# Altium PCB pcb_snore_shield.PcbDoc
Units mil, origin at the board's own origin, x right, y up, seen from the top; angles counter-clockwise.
Board outline 6000 x 4000 mil, 2 copper layers (Top Layer, Bottom Layer); 51 components, 37 nets, 162 pads, 19 vias.
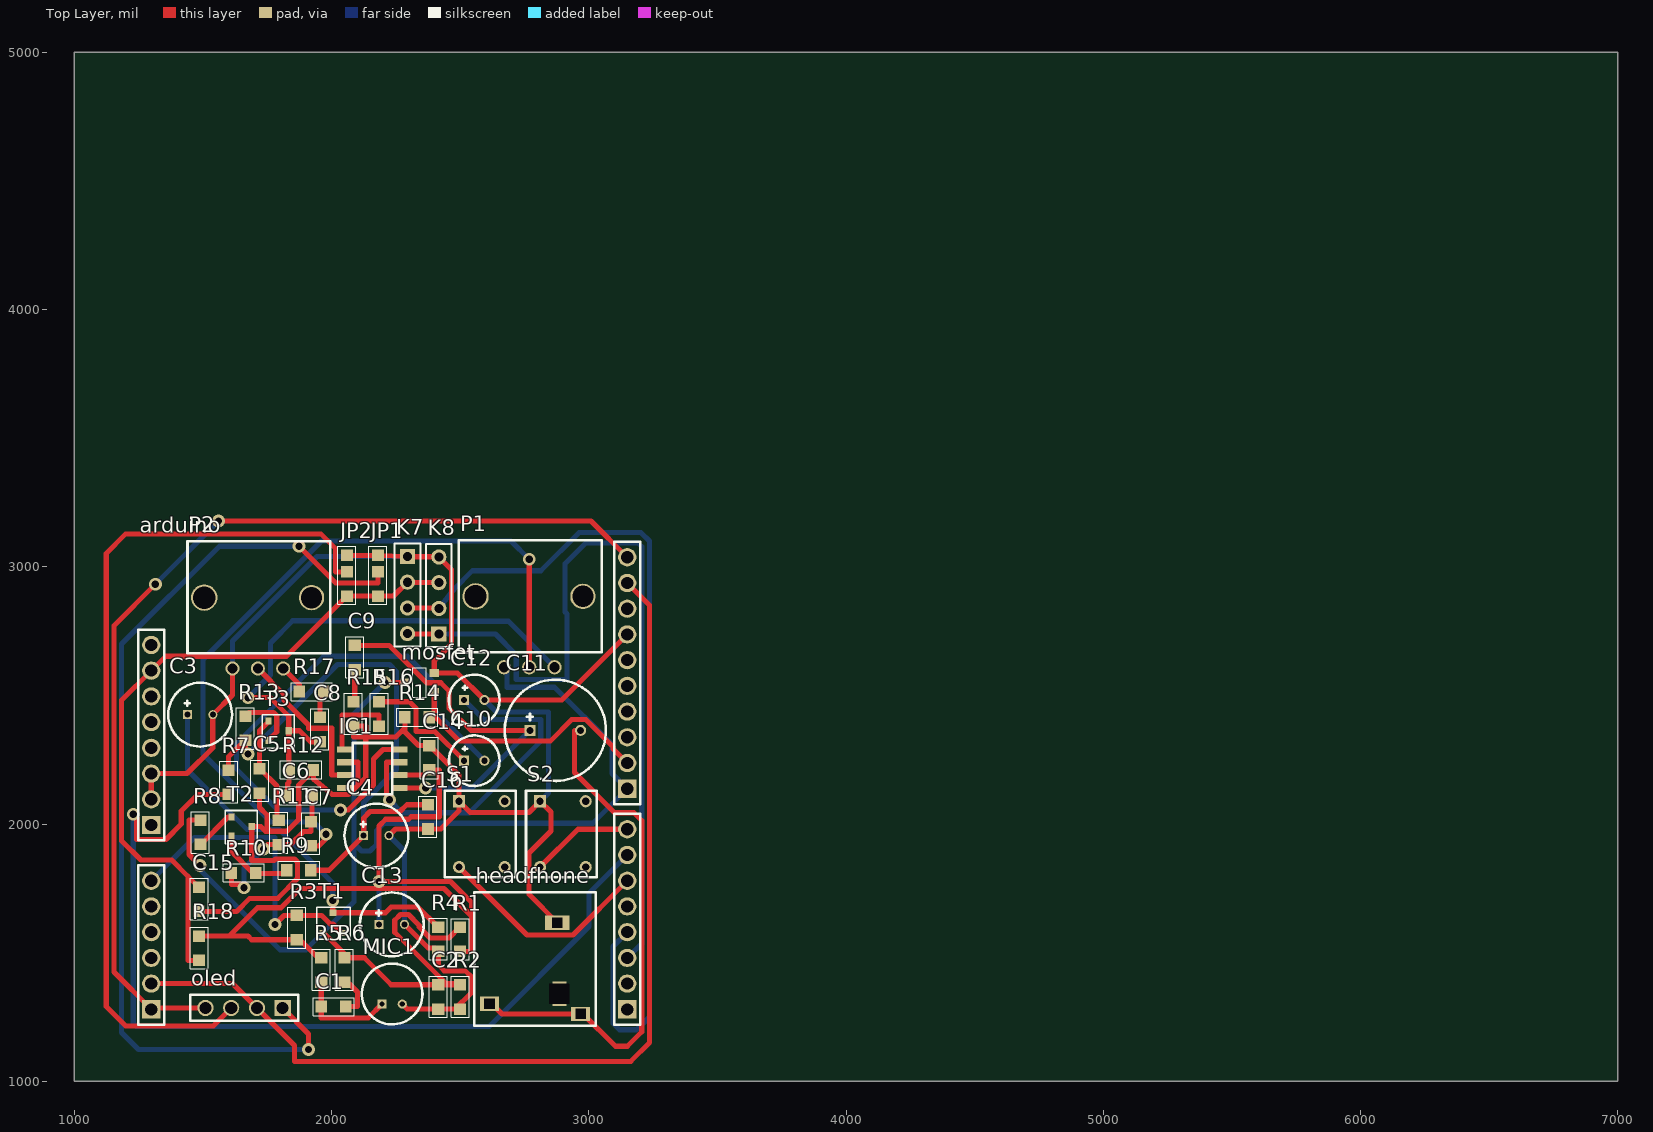
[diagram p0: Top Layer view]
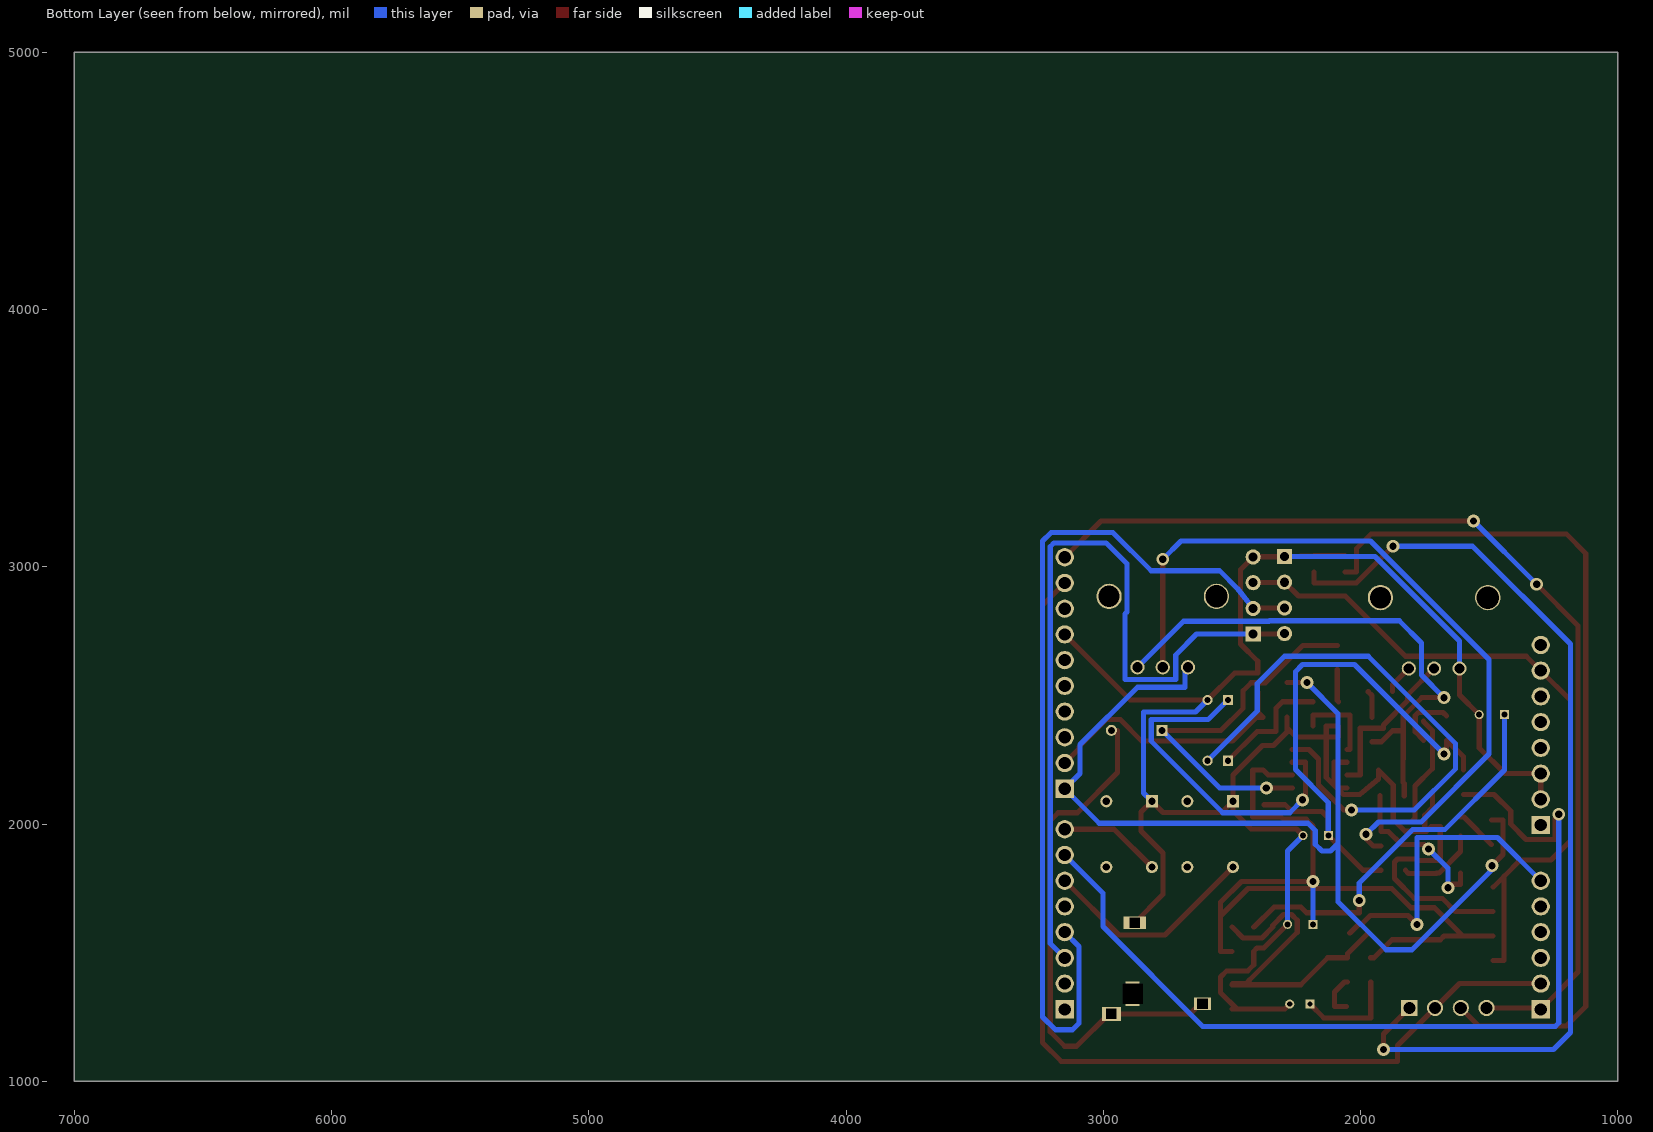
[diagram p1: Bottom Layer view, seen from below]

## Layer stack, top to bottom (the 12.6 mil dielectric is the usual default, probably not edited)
Top Solder: solder mask 0.4, Solder Resist, Dk 3.5
Top Layer: signal copper 1.4
Dielectric 1: dielectric 12.6, FR-4, Dk 4.8
Bottom Layer: signal copper 1.4
Bottom Solder: solder mask 0.4, Solder Resist, Dk 3.5

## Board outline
1000,1000 7000,1000 7000,5000 1000,5000

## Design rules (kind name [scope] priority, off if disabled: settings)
Clearance [All] p1: gap=10 ignorepadtopadclearanceinfootprint=FALSE except(0: Arc-Hole Track-Hole SMDPad-Hole THPad-Hole Via-Hole Fill-Hole Poly-Hole Region-Hole Text-Hole)
PolygonConnect [All] p1: connectstyle=Relief reliefconductorwidth=10 reliefentries=4 polygonreliefangle="90 Angle" airgapwidth=10
RoomDefinition snor_shield_sheet [InComponentClass('snor_shield_sheet')] p1: confinementstyle=ConfineIn formatcopy=TRUE lockcomponents=FALSE outline 7178.7,2815 20768.7,2815 20768.7,5240 7178.7,5240
RoutingVias [All] p1: holewidth=28 width=50 viastyle="Through Hole" minholewidth=28 minwidth=50 maxholewidth=28 maxwidth=50
SolderMaskExpansion [All] p1: expansion=4 istentingtop=FALSE
Width [All] p1: maxlimit=20 minlimit=20 preferedwidth=20
30 further rules are at their usual default settings.

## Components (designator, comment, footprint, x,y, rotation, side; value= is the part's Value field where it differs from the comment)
arduino "arduino r3 shield" arduino 1299.21,1279.53 r0 top
C1 "Capitor" "SMD 0805" 1948.19,1290 r0 top value=1µF
C2 "Capitor" "SMD 0805" 2415,1268.7 r90 top value=100nF
C3 "Cap Pol1" "elektor trans 2" 1440,2425 r0 top value=47µF/16V
C4 "Cap Pol1" "elektor trans 2" 2125,1955 r0 top value=47µF/16V
C5 "Capitor" "SMD 0805" 1720,2108.19 r90 top value=100pF
C6 "Capitor" "SMD 0805" 1818.19,2110 r0 top value=100pF
C7 "Capitor" "SMD 0805" 1920,1903.19 r90 top value=1nF
C8 "Capitor" "SMD 0805" 1955,2308.19 r90 top value=1µF
C9 "Capitor" "SMD 0805" 2090,2588.19 r90 top value=47nF
C10 "Cap Pol1" "elecktor trans 1" 2515.59,2245.98 r0 top value=10µF/16V
C11 "Cap Pol1" "elektor trans 3" 2771.5,2364.09 r0 top value=220µF/16V
C12 "Cap Pol1" "elecktor trans 1" 2515.59,2482.2 r0 top value=10µF/16V
C13 "Cap Pol1" "elektor trans 2" 2185,1610 r0 top value=47µF/16V
C14 "Cap" "SMD 0805" 2380,2316.81 r270 top value=100nF
C15 "Capitor" "SMD 0805" 1485,1648.19 r90 top value=100nF
C16 "Capitor" "SMD 0805" 2375,1968.7 r90 top value=100nF
headfhone "K-JACK-STEREO-3.5MM" adioplug3.5mm 2614.02,1301.1 r0 top
IC1 "LM386M-1/NOPB" LM386M-1/NOPB 2052.4,2290 r0 top
JP1 "Res2" soldeer_jumper 2180,2874.02 r90 top value=0Ohm
JP2 "Res2" soldeer_jumper 2060,2874.02 r90 top value=0Ohm
K7 "Header 4" HDR1X4 2295,3040 r270 top
K8 "Header 4" HDR1X4 2417.17,2738.11 r90 top (schematic designator K6)
MIC1 "Mic2" "Electret Condenser Microphone" 2196.26,1300 r0 top
mosfet "power MOSFET" "power mosfet" 2285,2550 r90 top
oled "1X4 socked" "oled scherm" 1810,1285 r180 top
P1 "Res Adj2" potmeter 2560,2885 r0 top value=100k
P2 "Res Adj2" potmeter 1505,2880 r0 top value=10K
R1 "weerstand" "SMD 0805" 2500,1611.3 r270 top value=27K
R2 "weerstand" "SMD 0805" 2500,1268.7 r90 top value=15K
R3 "weerstand" "SMD 0805" 1865,1656.3 r270 top value=27K
R4 "weerstand" "SMD 0805" 2415,1493.19 r90 top value=1K2
R5 "weerstand" "SMD 0805" 1960,1373.7 r90 top value=10K
R6 "weerstand" "SMD 0805" 2050,1373.7 r90 top value=680Ohm
R7 "weerstand" "SMD 0805" 1600,2103.19 r90 top value=10K
R8 "weerstand" "SMD 0805" 1490,2026.81 r270 top value=10K
R9 "weerstand" "SMD 0805" 1813.7,1820 r0 top value=10K
R10 "weerstand" "SMD 0805" 1598.7,1810 r0 top value=180K
R11 "weerstand" "SMD 0805" 1795,2026.3 r270 top value=180K
R12 "weerstand" "SMD 0805" 1941.3,2210 r180 top value=10K
R13 "weerstand" "SMD 0805" 1665,2431.3 r270 top value=1K
R14 "weerstand" "SMD 0805" 2273.7,2415 r0 top value=100K
R15 "weerstand" "SMD 0805" 2085,2368.7 r90 top value=10Ohm
R16 "weerstand" "SMD 0805" 2185,2368.7 r90 top value=1K
R17 "Res2" "SMD 0805" 1863.19,2515 r0 top value=100K
R18 "weerstand" "SMD 0805" 1485,1458.19 r90 top value=10Ohm
S1 "SW-PB" switch 2495.91,2088.5 r0 top
S2 "SW-PB" switch 2810.87,2088.5 r0 top
T1 "BC847C" "bipolar BjT" 2042.4,1576.26 r180 top
T2 "BC847C" "bipolar BjT" 1611.26,1952.6 r90 top
T3 "BC847C" "bipolar BjT" 1755,2325 r90 top

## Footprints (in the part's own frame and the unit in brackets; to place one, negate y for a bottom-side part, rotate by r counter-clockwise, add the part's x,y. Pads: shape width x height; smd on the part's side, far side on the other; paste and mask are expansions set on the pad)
adioplug3.5mm [mm]
  rect 1.4x2.4 hole 2 square: B(6.9,1)
  rect 1.9x1.4 hole 1 square: R(9,-1)
  rect 2.4x1.4 / inner rect 2.2x1.27 / far side rect 2.2x1.2 hole 1 square: S(6.7,8)
  rect 1.9x1.4 / inner rect 2.54x1.27 / far side rect 1.7x1.2 hole 1 square: T(0,0)
  silkscreen extent -1.5,-2.16 10.5,11
arduino [mm]
  round 1.8 hole 1.2: 3.3V(0,28.36) 5V(0,25.82) 14(0,35.98) A0/PC0(0,12.7) A1/PC1(0,10.16) A2/PC2(0,7.62) A3/PC3(0,5.08) A4/PC4(0,2.54) A4/PC4(47,42.1) A5/PC5(47,44.64) AREF(47,39.56) GND(0,20.74) GND(0,23.28) GND(47,37.02) INT0/PD2(47,5.08) INT1/PD3(47,7.62) IOREF(0,33.44) MISO/PB4(47,31.94) MOSI/PB3(47,29.4) PB1(47,24.32) PD4(47,10.16) PD5(47,12.7) PD6(47,15.24) PD7(47,17.78) RST/PC6(0,30.9) SCK/PB5(47,34.48) SS/PB2(47,26.86) TX/PD1(47,2.54)
  rect 1.8x1.8 hole 1.2: A5/PC5(0,0) PB0(47,21.78) RX/PD0(47,0) VIN(0,18.2)
  silkscreen extent -1.27,-1.52 48.27,46.16
"bipolar BjT" [mm]
  rect 0.7x0.6 smd: 1(1.9,0) 2(0,0) 3(0.95,-2)
  silkscreen extent -0.76,-2.54 2.54,0.63
"elecktor trans 1" [mm]
  rect 1x1 hole 0.6: 1(0,0)
  round 1 hole 0.6: 2(2,0)
  silkscreen extent -1.5,-2.5 3.5,2.5
"Electret Condenser Microphone" [mm]
  rect 0.9x0.9 hole 0.5: 1(0,0)
  round 0.9 hole 0.5: 2(2,0)
  silkscreen extent -2,-2 4,4
"elektor trans 2" [mm]
  rect 0.9x0.9 hole 0.6: 1(0,0)
  round 0.9 hole 0.6: 2(2.5,0)
  silkscreen extent -1.9,-3.15 4.4,3.15
"elektor trans 3" [mm]
  rect 1.1x1.1 hole 0.7: 1(0,0)
  round 1.1 hole 0.7: 2(5,0)
  silkscreen extent -2.5,-5 7.5,5
HDR1X4 [mm] "Connector; Header; 4 Position"
  rect 1.5x1.5 hole 0.9: 1(0,0)
  round 1.5 hole 0.9: 2(2.54,0) 3(5.08,0) 4(7.62,0)
  silkscreen extent -1.27,-1.27 8.89,1.27
LM386M-1/NOPB [mm]
  rect 1.55x0.6 smd: 1(0,0) 2(0,-1.27) 3(0,-2.54) 4(0,-3.81) 5(5.4,-3.81) 6(5.4,-2.54) 7(5.4,-1.27) 8(5.4,0)
  silkscreen extent 0.75,-4.44 4.65,0.64
"oled scherm" [mm]
  rect 1.6x1.6 hole 1.2: 1(0,0)
  round 1.6 hole 1.2: 2(5.08,0) 3(7.62,0) 4(2.54,0)
  silkscreen extent -1.52,-1.29 9.14,1.25
potmeter [mm]
  round 1.4 hole 1: 1(2.8,-7) 2(5.3,-7)
  round 1.4 / inner oval 1.4x0.064 / far side round 1.4 hole 1: 3(7.8,-7)
  round 2.5 / inner oval 2.5x0.064 / far side round 2.5 hole 2.1: 4(10.6,0)
  round 2.6 / inner round 2.5 / far side round 2.5 hole 2.2: 5(0,0)
  silkscreen extent -1.65,-5.5 12.45,5.55
"power mosfet" [mm]
  rect 0.8x0.9 smd: 1(-0.95,-2.9) 2(0.95,-2.9) 3(0,0)
  silkscreen extent -1.45,-2.1 1.45,-0.8
"SMD 0805" [mm]
  rect 1.14x1.2 smd: 1(0.3,0) 2(2.7,0)
  silkscreen extent -0.51,-0.89 3.56,0.89
soldeer_jumper [mm]
  rect 1.14x1.2 smd: 1(0.3,0) 2(2.7,0) 3(4.318,0)
  silkscreen extent -0.51,-0.89 5.21,0.89
switch [mm]
  rect 1.2x1.2 hole 0.71: 1(0,0)
  round 1.2 hole 0.71: 2(0,-6.5) 3(4.5,-6.5) 4(4.5,0)
  silkscreen extent -1.4,-7.49 5.59,1.02

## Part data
C1 C2 C5 C6 C7 C8 C9 C15 C16: "Capacitor"
C3 C4 C13: library part "Cap Pol1_1", "Polarized Capacitor (Radial) 47µF"
C10 C12: "Polarized Capacitor (Radial) 10µF"
C11: library part "Cap Pol1_2", "Polarized Capacitor (Radial) 220µF"
C14: library part Capitor, "Capacitor"
JP1 JP2: library part solderjump, "Resistor"
K7: "Header, 4-Pin,2mm"
K8: "Header, 4-Pin"
MIC1: "Microphone"
P1: "Variable Resistor 10K"
P2: library part "Res Adj2_1", "Variable Resistor"
R1 R2 R3 R4 R5 R6 R7 R8 R9 R10 R11 R12 R13 R14 R15 R16 R18: "Resistor"
R17: library part weerstand, "Resistor"
S1 S2: library part switch, "Switch"
T1 T2 T3: library part BJT, "NPN General Purpose Amplifier"

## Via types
v1: diameter 50, hole 28, Top Layer to Bottom Layer, 19 vias

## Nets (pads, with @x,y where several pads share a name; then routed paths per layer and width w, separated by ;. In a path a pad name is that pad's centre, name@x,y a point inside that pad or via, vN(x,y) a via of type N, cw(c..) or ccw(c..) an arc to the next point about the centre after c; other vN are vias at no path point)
+5V: C13.1 C14.2 IC1.6 R1.2 R3.2 R5.2 R18.2 | length 3176.2
  Top Layer w20: R18.2 1602.14,1564.49 ; R5.2 1947,1480 1877,1550 R3.2 1689.49,1550 1675,1564.49 1602.14,1564.49 ; IC1.6 2358.31,2190 2378.82,2210.51 C14.2 2419,2210.51 2419,2028 2309.53,2028 2299.71,2018.19 2210.89,2018.19 2185,1992.29 v1(2185,1777) 2463,1777 2544,1696 2544,1642 ; R1.2 2544,1505 2544,1642 ; 1602.14,1564.49 1712.14,1674.49 1803.49,1674.49 1878,1749 2437,1749 2544,1642
  Bottom Layer w20: C13.1 v1(2185,1777)
GND: arduino.GND C2.1 C3.2 C4.2 C5.1 C12.2 C13.2 C14.1 C15.1 C16.1 headfhone.S IC1.2 IC1.4 JP1.3 JP2.3 K7.1 K8.4 MIC1.2 mosfet.2 P2.1 R2.1 R4.1 R12.1 R14.1 R15.1 S1.1 S2.1 T2.3 | length 9249.8
  Top Layer w20: arduino.GND@1299.21,2096.06 1299.21,2196.06 1438.62,2196.06 1538.43,2295.87 C3.2 1615.24,2501.81 P2.1 ; C15.1 1631.2,1660 1682.14,1710.94 1790.8,1710.94 1867.95,1788.09 1867.95,1851.91 1856.24,1863.62 1781.97,1863.62 1775.98,1857.63 1690,1857.63 T2.3 1725.05,1990 1743,1972.05 1763.09,1972.05 ; C5.1 1720,2064.4 1750,2034.4 1750,1985.14 1763.09,1972.05 ; R12.1 R12.1@1929.49,2208.82 ; IC1.4 2092.31,2140 ; IC1.2 2103,2240 2103,2150.69 ; JP2.3 JP1.3 K7.1 2295.94,3039.06 2416.22,3039.05 K8.4 2466.69,2988.58 2466.69,2700.3 2399.17,2632.78 mosfet.2 2489.13,2587.4 C12.2 2894.8,2482.2 arduino.GND@3149.61,2737.01 ; C4.2 2248.94,1980.51 C16.1 2425,1980.51 2495.91,2051.42 S1.1 ; MIC1.2 2294.49,1280.51 C2.1 2416.18,1280.51 R2.1@2479.86,1280.51 ; C13.2 2375.99,1517.44 2402.56,1517.44 R4.1 2415,1452.56 2438.42,1429.14 2520.21,1429.14 2543.62,1405.73 2543.62,1344.27 R2.1@2479.86,1280.51 ; R14.1 2285.51,2373.51 ; R2.1 R2.1@2479.86,1280.51 ; headfhone.S 2767.24,1726.62 2767.24,1887.8 2852.77,1973.33 2852.77,2046.6 S2.1 2767.24,2044.88 2539.53,2044.88 S1.1 ; 1763.09,1972.05 1826.91,1972.05 1872.44,2017.58 1872.44,2151.77 R12.1@1929.49,2208.82 ; R12.1@1929.49,2208.82 1929.49,2176 2003,2114 2066.31,2114 2092.31,2140 ; 2092.31,2140 2103,2150.69 ; 2103,2150.69 2133,2180.69 2133,2338 ; 2133,2338 2133,2380.51 R15.1 2085,2338 2133,2338 ; 2133,2338 2250,2338 2285.51,2373.51 ; 2285.51,2373.51 2285.51,2357.49 2338,2305 C14.1 2381.18,2305 2495.91,2190.28 S1.1
  Bottom Layer w20: P2.1 1615.24,2711.24 1944,3040 K7.1 ; C4.2 2283.43,1895 C13.2 ; C12.2 2640.79,2435.75 2843.15,2435.75 2843.15,2120.79 S2.1
Netarduino_A0/PC0: arduino.A0/PC0 R3.1 T1.2 | length 1194.9
  Top Layer w20: v1(1780,1609) 1815.49,1644.49 R3.1 1961.64,1644.49 1994.85,1611.28 2005.41,1611.28 2040.43,1576.26 T1.2
  Bottom Layer w20: arduino.A0/PC0 1467.69,1948 1780,1948 v1(1780,1609)
Netarduino_A4/PC4: arduino.A4/PC4 oled.4 | length 3950.9
  Top Layer w20: arduino.A4/PC4@1299.21,1379.53 1615.47,1379.53 oled.4 1856.27,1138.73 1856.27,1077.28 3163.28,1077.28 3236,1150 3236,2850.61 arduino.A4/PC4@3149.61,2937.01
Netarduino_A5/PC5: arduino.A5/PC5 oled.3 | length 3987.3
  Top Layer w20: v1(1315,2932) 1154,2771 1154,1424.74 1299.21,1279.53 1304.69,1285 oled.3 ; v1(1561,3178) 3008.61,3178 arduino.A5/PC5@3149.61,3037.01
  Bottom Layer w20: v1(1315,2932) v1(1561,3178)
Netarduino_INT0/PD2: arduino.INT0/PD2 K7.4 K8.1 | length 3162.2
  Top Layer w20: K7.4 2295.95,2739.06 2416.22,2739.06 K8.1
  Bottom Layer w20: K8.1 2637,2738.11 2718.11,2657 2718.11,2561.85 2915,2561.85 2915,2817 2908,2824 2908,3012 2989,3093 3191,3093 3206,3078 3206,1535.92 arduino.INT0/PD2
Netarduino_INT1/PD3: arduino.INT1/PD3 K7.3 K8.2 | length 3483.2
  Top Layer w20: K7.3 2295.95,2839.06 2416.22,2839.06 K8.2
  Bottom Layer w20: K8.2 2479,2916 2547.34,2984.34 2813.66,2984.34 2961.86,3132.54 3203.46,3132.54 3236,3100 3236,1250 3186,1200 3119,1200 3094,1225 3094,1523.92 arduino.INT1/PD3
Netarduino_IOREF: arduino.IOREF C15.2 JP1.1 JP2.1 K7.2 K8.3 R18.1 | length 2805.2
  Top Layer w20: R18.1 1441.38,1470 1441.38,1796.93 ; C15.2 1483.82,1754.49 1441.38,1796.93 ; K8.3 2416.22,2939.06 2295.95,2939.06 K7.2 2240.83,2885.83 JP1.1 JP2.1 2058.82,2885.83 1824.96,2651.97 1355.12,2651.97 arduino.IOREF 1184,2480.85 1184,1934.62 1258.98,1859.64 1378.67,1859.64 ; 1378.67,1859.64 1441.38,1796.93 ; 1378.67,1859.64 1441.38,1796.93
Netarduino_PB0: arduino.PB0 mosfet.3 P1.1 R8.1 | length 4024.1
  Top Layer w20: v1(1489,1838) 1446,1881 1446,2015 R8.1 ; v1(2208,2550) mosfet.3
  Bottom Layer w20: v1(1489,1838) 1489,1822 1800,1511 1900,1511 2087,1698 2087,1925 ; v1(2208,2550) 2087,2429 2087,1925 ; P1.1 2682.71,2596.94 2682.71,2531.85 2867.05,2531.85 3089.99,2308.91 3089.99,2196.62 arduino.PB0 3015.6,2003 2204,2003 2176,1975 2176,1921 2150,1895 2117,1895 2087,1925
Netarduino_PB1: arduino.PB1 mosfet.1 R14.2 | length 1022.8
  Top Layer w20: mosfet.1 2399.17,2435.36 2380,2416.18 R14.2 2404,2415 2497,2322 2850,2322 2934,2406 2988,2406 3094,2300 3094,2292.61 arduino.PB1
Netarduino_PD5: arduino.PD5 S1.2 | length 850.5
  Top Layer w20: S1.2 2760,1568.5 2938.58,1568.5 arduino.PD5
Netarduino_PD6: arduino.PD6 R7.1 | length 3652.2
  Top Layer w20: v1(1229,2038) 1243,2024 1243,1940 1356,1940 1416,2000 1416,2050 1481,2115 R7.1
  Bottom Layer w20: v1(1229,2038) 1229,1227 1243,1213 2613,1213 3001,1601 3001,1730.92 arduino.PD6
Netarduino_PD7: arduino.PD7 S2.2 | length 399.6
  Top Layer w20: S2.2 2957.8,1979.53 arduino.PD7
NetC1_1: C1.1 MIC1.1 R5.1 | length 397.6
  Top Layer w20: R5.1 C1.1 1960,1246.38 2142.64,1246.38 MIC1.1
NetC1_2: C1.2 R6.1 | length 170.5
  Top Layer w20: R6.1 2062.22,1385.51 2101.17,1346.57 2101.17,1290 C1.2
NetC2_2: C2.2 R1.1 R2.2 R6.2 T1.1 | length 1332.7
  Top Layer w20: T1.1 1969.57,1576.26 2050,1495.83 R6.2 2127,1480 2232,1375 C2.2 R2.2 2496.25,1378.75 2446.38,1378.75 2432.57,1392.57 2245.71,1579.42 2245.71,1625.62 2267.8,1647.72 2299.05,1647.72 2341.07,1605.69 2341.07,1599.07 2383.09,1557.05 2456.38,1557.05 2498.82,1599.49 R1.1
NetC3_1: C3.1 R4.2 T1.3 | length 1529.7
  Top Layer w20: v1(2005,1703) T1.3 2209.28,1655 2232,1677.72 2335.59,1677.72 2413.82,1599.49 R4.2
  Bottom Layer w20: C3.1 1440,2210 1672,1978 1798,1978 2005,1771 v1(2005,1703)
NetC4_1: C4.1 C16.2 R7.2 R9.2 R13.2 | length 2224.6
  Top Layer w20: R7.2 1600,2261.18 1663.82,2325 R13.2 1665,2282 v1(1675,2272) ; R9.2 1990,1820 C4.1 2125,2023.19 2150,2048.19 2266,2048.19 2292.81,2075 C16.2
  Bottom Layer w20: v1(1675,2272) 2023,2620 2225,2620 2253,2592 2253,2211.48 2125,2083.48 C4.1
NetC5_2: C5.2 R11.1 T3.1 | length 431.6
  Top Layer w20: T3.1 1755,2397.84 1720,2362.84 C5.2 1721.18,2214.49 1787.56,2148.11 1787.56,2021.93 R11.1
NetC6_1: C6.1 C8.1 P1.3 R12.2 T3.3 | length 2102.4
  Top Layer w20: v1(1675,2491.08) 1761.63,2491.08 1833.74,2418.97 T3.3 ; C6.1 1830,2157 1835,2162 R12.2 1833.74,2287.26 T3.3 ; C8.1 1917.95,2320 1875.55,2362.4 T3.3
  Bottom Layer w20: v1(1675,2491.08) 1763,2579.08 1763,2704 1849,2790 2354,2790 2356,2788 2688.5,2788 P1.3
NetC6_2: C6.2 C7.2 R10.1 R11.2 | length 635.4
  Top Layer w20: R10.1 1610.51,1766 1646,1766 v1(1660,1752) ; v1(1735,1903) 1752,1920 R11.2 1841,1920 1892,1971 1920,1971 C7.2 1924.49,2013.98 C6.2
  Bottom Layer w20: v1(1660,1752) 1660,1828 v1(1735,1903)
NetC7_1: C7.1 P1.2 | length 2969.6
  Top Layer w20: C7.1 1950,1915 1978,1943 v1(1978,1960) ; P1.2 v1(2768.66,3029.34)
  Bottom Layer w20: v1(1978,1960) 1930,2008 1764,2008 1500,2272 1500,2639 1961,3100 2698,3100 v1(2768.66,3029.34)
NetC8_2: C8.2 R17.2 | length 106.5
  Top Layer w20: C8.2 1955,2499.33 1969.49,2513.82 R17.2
NetC9_1: C9.1 R15.2 | length 127.1
  Top Layer w20: R15.2 2090,2480 C9.1
NetC9_2: C9.2 C11.1 IC1.5 | length 1457.5
  Top Layer w20: C9.2 2223.51,2694.49 2369,2549 2425,2549 2456,2518 2456,2450 2541.91,2364.09 C11.1 ; IC1.5 v1(2366,2140)
  Bottom Layer w20: v1(2366,2140) 2547.4,2140 C11.1
NetC10_1: C10.1 R16.2 | length 478.8
  Top Layer w20: R16.2 2303,2475 2328,2450 2328,2359 2402.57,2359 C10.1
NetC10_2: C10.2 IC1.8 | length 2291.5
  Top Layer w20: v1(2035,2054) 2065.15,2054 2163,2151.85 2163,2253 2200,2290 IC1.8
  Bottom Layer w20: v1(2035,2054) 1791,2054 1630,2215 1630,2312 1970,2652 2295,2652 2401,2546 2401,2439.31 C10.2
NetC11_2: C11.2 headfhone.R headfhone.T | length 2032.5
  Top Layer w20: headfhone.T 2623.86,1301.1 2663.23,1261.73 headfhone.R 2978,1261.73 3103.73,1136 3150,1136 3206,1192 3206,2013 3175,2044 3100,2044 2944,2200 2944,2364.09 C11.2
NetC12_1: C12.1 IC1.7 | length 1338.5
  Top Layer w20: v1(2225,2094) 2214,2105 2214,2240 IC1.7
  Bottom Layer w20: v1(2225,2094) 2275,2044 2535.15,2044 2813.15,2322 2813.15,2405.75 2592.05,2405.75 C12.1
NetIC1_1: IC1.1 R16.1 | length 332.9
  Top Layer w20: IC1.1 2041,2290 2041,2424 2185,2424 R16.1
NetIC1_3: IC1.3 P2.2 | length 637.6
  Top Layer w20: P2.2 1816,2502.07 1816,2480 1911,2385 1911,2372 2001,2372 2001,2190 IC1.3
NetJP1_2: JP1.2 oled.1 | length 3725.1
  Top Layer w20: oled.1 1911,1184 v1(1911,1123) ; v1(1873,3080) 2016,2937 2180,2937 JP1.2
  Bottom Layer w20: v1(1873,3080) 1564,3080 1184,2700 1184,1189 1250,1123 v1(1911,1123)
NetJP2_2: JP2.2 oled.2 | length 3388.7
  Top Layer w20: oled.2 1540,1215 1200,1215 1124,1291 1124,3052 1200,3128 1958,3128 2016,3070 2016,2980.31 JP2.2
NetP2_3: P2.3 R17.1 | length 115.5
  Top Layer w20: P2.3 1875,2541.5 R17.1
NetR8_2: R8.2 T2.1 | length 165.5
  Top Layer w20: R8.2 1491.18,1920.51 1598.07,2027.4 T2.1
NetR9_1: R9.1 R10.2 T2.2 | length 315.8
  Top Layer w20: T2.2 1611.26,1892.88 1694.14,1810 R10.2 1705,1807.63 1813.14,1807.63 R9.1
NetR13_1: R13.1 T3.2 | length 242.5
  Top Layer w20: R13.1 1679.1,2433.58 1775.1,2433.58 1786.81,2421.87 1786.81,2358.78 1755,2326.97 T3.2
pads on no net: arduino.3.3V arduino.5V arduino.14 arduino.A1/PC1 arduino.A2/PC2 arduino.A3/PC3 arduino.AREF arduino.MISO/PB4 arduino.MOSI/PB3 arduino.PD4 arduino.RST/PC6 arduino.RX/PD0 arduino.SCK/PB5 arduino.SS/PB2 arduino.TX/PD1 arduino.VIN headfhone.B P1.4 P1.5 P2.4 P2.5 S1.3 S1.4 S2.3 S2.4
